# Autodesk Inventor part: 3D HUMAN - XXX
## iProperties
Category: PART
Company: Cross Bros.
Shininess: 64.0
Length Units: 11272
Angle Units: 11279
Time Units: 11290
Mass Units: 11286
Length Display Precision: 3
Angle Display Precision: 2
Compacted: True
Part Number: 3D HUMAN - XXX
Document SubType Name: Modeling
Created: 2003-03
Designer: MVF
Catalog Web Link: www.crossbros.com
Density: 0.0
Volumn: 0.0
Area: 0.0
PropertySet Name: Model Information
Control State: 0
Master: False
Checked Out: False
Author: MVF
Title: iMike
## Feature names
1. Revolution1
